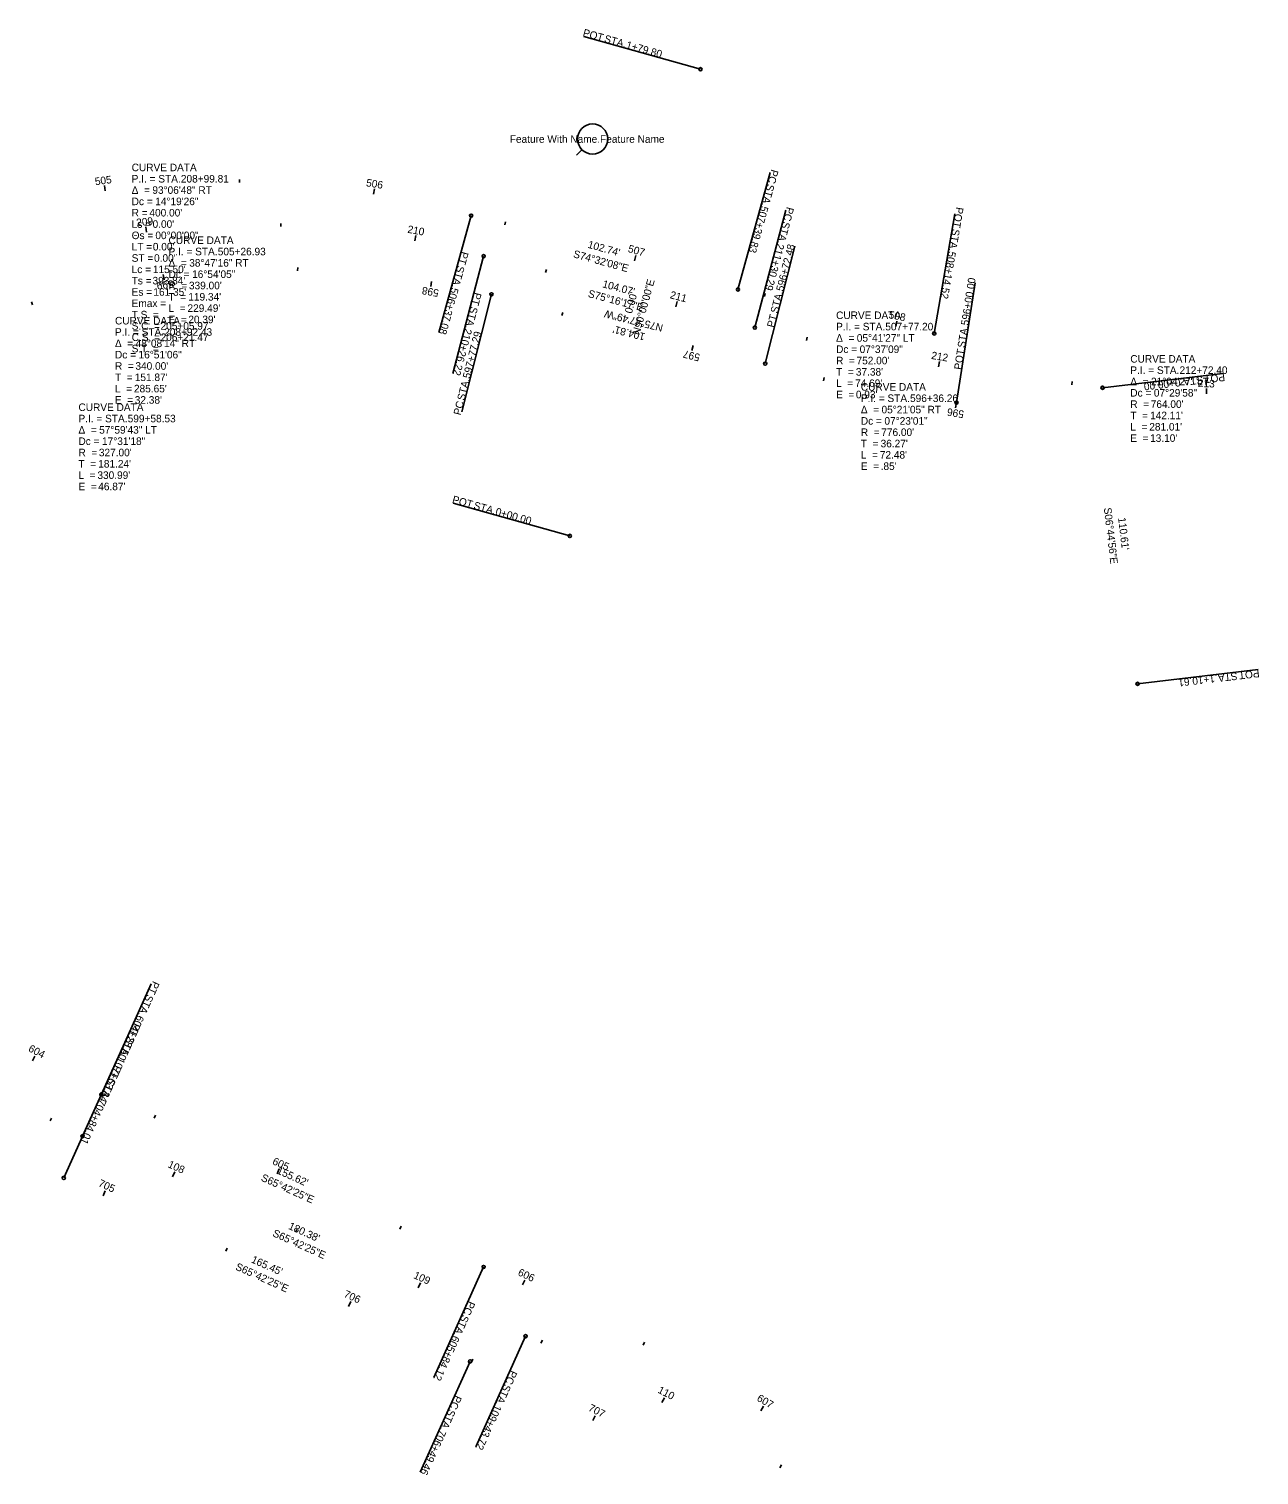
# Model space of a CAD drawing. Extents: x 1600023 to 1602131, y 285824 to 287284.
# Drawn here: x 1601230 to 1601686, y 286324 to 286860 of the extents above; entities that cross this region are included whole.
import ezdxf

# ---------------------------------------------------------------- set-up
doc = ezdxf.new("R2010")
doc.units = 0
for name, color, linetype in [('_CIVIL_CONSTRUCTION', 7, 'Continuous'), ('Default', 7, 'Continuous'), ('GE_P_Alignment', 7, 'Continuous'), ('PF_P_Grade_Line', 7, 'Continuous'), ('PF_X_Ground_Line', 7, 'Continuous'), ('PV_P_Curb', 7, 'Continuous'), ('SC_Scratch6', 7, 'Continuous'), ('SC_Scratch8', 7, 'Continuous')]:
    doc.layers.add(name, color=color, linetype=linetype)

msp = doc.modelspace()

# ---------------------------------------------------------------- linework, layer by layer
at = {"layer": '_CIVIL_CONSTRUCTION'}
for p, q in [((1601478.79, 286845.09), (1601435.46, 286857.22)), ((1601498.97, 286749.25), (1601510.41, 286792.77)), ((1601398.32, 286775.71), (1601386.88, 286732.19)), ((1601628.02, 286726.93), (1601672.71, 286732.22)), ((1601430.3, 286671.95), (1601386.97, 286684.09)), ((1601641.02, 286617.09), (1601685.71, 286622.38)), ((1601249.47, 286449.29), (1601267.99, 286490.31)), ((1601413.89, 286375.08), (1601395.37, 286334.07))]:
    msp.add_line(p, q, dxfattribs=at)
for centre in [(1601478.79, 286845.09), (1601398.32, 286775.71), (1601498.97, 286749.25), (1601628.02, 286726.93), (1601430.3, 286671.95), (1601641.02, 286617.09), (1601249.47, 286449.29), (1601413.89, 286375.08)]:
    msp.add_circle(centre, 0.6, dxfattribs=at)
at = {"layer": 'Default'}
for p, q in [((1601492.7, 286763.37), (1601504.69, 286806.74)), ((1601257.83, 286799.98), (1601257.57, 286801.96)), ((1601307.7, 286803.01), (1601307.71, 286804.21)), ((1601357.46, 286798.68), (1601357.78, 286800.65)), ((1601393.67, 286790.76), (1601381.67, 286747.39)), ((1601565.55, 286747.06), (1601573.19, 286791.41)), ((1601406.12, 286787.32), (1601406.44, 286788.48)), ((1601502.81, 286735.86), (1601513.85, 286779.49)), ((1601454.31, 286773.99), (1601454.84, 286775.92)), ((1601279.43, 286768.93), (1601279.69, 286766.94)), ((1601329.32, 286771.47), (1601329.29, 286770.27)), ((1601379.01, 286766.38), (1601378.66, 286764.42)), ((1601573.8, 286721.39), (1601580.73, 286765.85)), ((1601230.51, 286758.82), (1601230.85, 286757.66)), ((1601401.2, 286761.58), (1601390.16, 286717.96)), ((1601502.52, 286760.72), (1601502.82, 286761.88)), ((1601427.66, 286754.89), (1601427.36, 286753.72)), ((1601551.27, 286749.66), (1601551.65, 286751.63)), ((1601476.13, 286742.62), (1601475.64, 286740.68)), ((1601524.68, 286730.67), (1601524.42, 286729.49)), ((1601573.8, 286721.39), (1601573.49, 286719.41)), ((1601256.47, 286464.79), (1601274.98, 286505.8)), ((1601230.83, 286477.21), (1601231.75, 286478.99)), ((1601242.48, 286433.8), (1601260.99, 286474.81)), ((1601276.07, 286455.94), (1601276.56, 286457.03)), ((1601321.64, 286435.37), (1601322.46, 286437.19)), ((1601257.06, 286427.22), (1601257.88, 286429.04)), ((1601367.21, 286414.8), (1601367.71, 286415.89)), ((1601302.63, 286406.65), (1601303.12, 286407.74)), ((1601398.31, 286400.76), (1601379.8, 286359.75)), ((1601412.74, 286394.12), (1601413.59, 286395.93)), ((1601348.2, 286386.08), (1601349.03, 286387.9)), ((1601457.48, 286371.82), (1601458.04, 286372.88)), ((1601393.78, 286365.51), (1601394.27, 286366.6)), ((1601393.28, 286365.73), (1601374.77, 286324.71)), ((1601438.83, 286343.83), (1601439.74, 286345.61)), ((1601501.14, 286347.45), (1601502.15, 286349.17))]:
    msp.add_line(p, q, dxfattribs=at)
for centre in [(1601393.67, 286790.76), (1601492.7, 286763.37), (1601401.2, 286761.58), (1601565.55, 286747.06), (1601502.81, 286735.86), (1601573.8, 286721.39), (1601256.47, 286464.79), (1601242.48, 286433.8), (1601398.31, 286400.76), (1601393.28, 286365.73)]:
    msp.add_circle(centre, 0.6, dxfattribs=at)
at = {"layer": 'PV_P_Curb'}
msp.add_circle((1601438.76, 286819.18), 5.6, dxfattribs=at)
at = {"layer": 'SC_Scratch6'}
for p, q in [((1601273.15, 286784.67), (1601272.92, 286786.65)), ((1601323.06, 286786.69), (1601323.1, 286787.89)), ((1601372.73, 286781.39), (1601373.09, 286783.36)), ((1601421.32, 286769.66), (1601421.63, 286770.82)), ((1601469.68, 286756.95), (1601470.19, 286758.88)), ((1601518.1, 286744.48), (1601518.37, 286745.65)), ((1601567.11, 286734.62), (1601567.44, 286736.6)), ((1601616.66, 286727.99), (1601616.78, 286729.18)), ((1601666.53, 286724.61), (1601666.6, 286726.61)), ((1601237.38, 286454.93), (1601237.91, 286456.01)), ((1601282.89, 286434.21), (1601283.71, 286436.03)), ((1601328.46, 286413.64), (1601328.95, 286414.73)), ((1601374.03, 286393.07), (1601374.86, 286394.89)), ((1601419.6, 286372.48), (1601420.1, 286373.57)), ((1601464.5, 286350.5), (1601465.42, 286352.27)), ((1601508.25, 286326.3), (1601508.85, 286327.33))]:
    msp.add_line(p, q, dxfattribs=at)
at = {"layer": 'SC_Scratch8'}
msp.add_line((1601432.76, 286813.18), (1601434.8, 286815.22), dxfattribs=at)
msp.add_lwpolyline([(1601432.76, 286813.18), (1601433.47, 286813.89), (1601433.47, 286813.89)], close=True, dxfattribs=at)

# ---------------------------------------------------------------- texts
at = {"layer": '_CIVIL_CONSTRUCTION'}
for s, rotation, p in [('POT', 344.3549, (1601434.93, 286857.42)), (' STA. ', 344.3549, (1601441.86, 286855.47)), ('1+79.80', 344.3549, (1601450.96, 286852.92)), ('PC', 255.2715, (1601510.83, 286794.17)), (' STA. ', 255.2715, (1601509.66, 286789.74)), ('211+30.29', 255.2715, (1601507.26, 286780.6)), ('PT', 255.2715, (1601394.89, 286762.48)), (' STA. ', 255.2715, (1601393.77, 286758.21)), ('210+26.22', 255.2715, (1601391.36, 286749.07)), (' STA. ', 186.7488, (1601666.13, 286731.4)), ('POT', 186.7488, (1601673.28, 286732.24)), ('0+00.00', 186.7488, (1601656.74, 286730.29)), ('POT', 344.3549, (1601386.44, 286684.28)), (' STA. ', 344.3549, (1601393.37, 286682.34)), ('0+00.00', 344.3549, (1601402.47, 286679.79)), ('1+10.61', 186.7488, (1601669.54, 286620.42)), (' STA. ', 186.7488, (1601678.93, 286621.53)), ('POT', 186.7488, (1601686.08, 286622.38)), ('PT', 245.7068, (1601268.57, 286491.5)), (' STA. ', 245.7068, (1601266.76, 286487.48)), ('107+63.34', 245.7068, (1601262.87, 286478.86)), ('PC', 245.7068, (1601408.34, 286362.69)), (' STA. ', 245.7068, (1601406.45, 286358.51)), ('109+43.72', 245.7068, (1601402.56, 286349.9))]:
    msp.add_text(s, height=2.8, rotation=rotation, dxfattribs=at).set_placement(p)
at = {"layer": 'Default'}
for s, rotation, p in [('PC', 254.5355, (1601505.11, 286808.09)), ('505', 7.7047, (1601254.22, 286802.01)), ('506', 350.8033, (1601354.55, 286801.69)), (' STA. ', 254.5355, (1601503.89, 286803.67)), ('507+39.83', 254.5355, (1601501.37, 286794.57)), ('POT', 260.2263, (1601573.7, 286794.09)), (' STA. ', 260.2263, (1601572.48, 286786.99)), ("102.74'", 344.5355, (1601436.76, 286778.89)), ('507', 344.5355, (1601451.68, 286777.31)), ('596+72.48', 75.7969, (1601509.51, 286762.51)), ('PT', 254.5355, (1601390.09, 286777.64)), ('S74°32\'08"E', 344.5355, (1601431.36, 286775.36)), ('508+14.52', 260.2263, (1601570.87, 286777.68)), (' STA. ', 254.5355, (1601388.91, 286773.39)), ('599', 187.2981, (1601283.04, 286766.87)), ('598', 169.7764, (1601381.85, 286763.33)), ('506+37.08', 254.5355, (1601386.39, 286764.28)), ('596+00.00', 81.1483, (1601578.2, 286749.9)), (' STA. ', 75.7969, (1601507.19, 286753.34)), ('N75°47\'49"W', 165.7969, (1601465.12, 286750.35)), ('PT', 75.7969, (1601506.11, 286749.07)), ('508', 349.1202, (1601548.47, 286752.75)), ('597+77.29', 75.7969, (1601393.21, 286730.16)), ("104.81'", 165.7969, (1601458.47, 286747.04)), (' STA. ', 81.1483, (1601576.75, 286740.56)), ('597', 165.7969, (1601478.83, 286739.36)), ('POT', 81.1483, (1601575.64, 286733.45)), (' STA. ', 75.7969, (1601390.89, 286720.99)), ('PC', 75.7969, (1601389.76, 286716.55)), ('596', 171.1482, (1601576.73, 286718.4)), ('PT', 245.7068, (1601275.6, 286507.06)), (' STA. ', 245.7068, (1601273.78, 286503.04)), ('604+28.50', 245.7068, (1601269.89, 286494.43)), ('604', 332.5732, (1601229.08, 286480.94)), ('PT', 245.7068, (1601261.53, 286475.9)), (' STA. ', 245.7068, (1601259.71, 286471.87)), ('704+84.01', 245.7068, (1601255.83, 286463.26)), ('605', 335.7068, (1601319.66, 286439.01)), ("155.62'", 335.7068, (1601321.32, 286435.56)), ('705', 335.7068, (1601255.07, 286430.85)), ('S65°42\'25"E', 335.7068, (1601315.44, 286432.9)), ("165.45'", 335.7068, (1601311.81, 286402.55)), ('S65°42\'25"E', 335.7068, (1601305.94, 286399.89)), ('606', 334.8531, (1601410.76, 286397.81)), ('706', 335.7068, (1601346.17, 286389.74)), ('PC', 245.7068, (1601392.76, 286388.37)), (' STA. ', 245.7068, (1601390.88, 286384.19)), ('605+84.12', 245.7068, (1601386.99, 286375.58)), ('PC', 245.7068, (1601387.77, 286353.41)), ('607', 329.4783, (1601499.46, 286351.33)), (' STA. ', 245.7068, (1601385.88, 286349.23)), ('707', 332.9279, (1601436.92, 286347.61)), ('706+49.46', 245.7068, (1601382, 286340.61))]:
    msp.add_text(s, height=2.8, rotation=rotation, dxfattribs=at).set_placement(p)
for s, p in [('CURVE DATA', (1601281.37, 286780.25)), ('Δ  = ', (1601281.37, 286771.85)), ('P.I. = STA. ', (1601281.37, 286776.05)), ('38°47\'16" RT', (1601289.05, 286771.85)), ('505+26.93', (1601299.64, 286776.05)), ('Dc = ', (1601281.37, 286767.65)), ('16°54\'05"', (1601290.11, 286767.65)), ('R  = ', (1601281.37, 286763.45)), ("339.00'", (1601288.95, 286763.45)), ('T  = ', (1601281.37, 286759.25)), ("119.34'", (1601288.71, 286759.25)), ('L  = ', (1601281.37, 286755.05)), ('E  = ', (1601281.37, 286750.85)), ("229.49'", (1601288.41, 286755.05)), ("20.39'", (1601288.71, 286750.85)), ('CURVE DATA', (1601529.12, 286752.41)), ('P.I. = STA. ', (1601529.12, 286748.21)), ('507+77.20', (1601547.39, 286748.21)), ('Δ  = ', (1601529.12, 286744.01)), ('Dc = ', (1601529.12, 286739.81)), ('05°41\'27" LT', (1601536.8, 286744.01)), ('07°37\'09"', (1601537.86, 286739.81)), ('R  = ', (1601529.12, 286735.61)), ("752.00'", (1601536.71, 286735.61)), ('T  = ', (1601529.12, 286731.41)), ("37.38'", (1601536.46, 286731.41)), ('L  = ', (1601529.12, 286727.21)), ('E  = ', (1601529.12, 286723.01)), ("74.69'", (1601536.17, 286727.21)), ("0.93'", (1601536.46, 286723.01)), ('CURVE DATA', (1601538.31, 286725.83)), ('CURVE DATA', (1601247.94, 286718.3)), ('P.I. = STA. ', (1601538.31, 286721.63)), ('596+36.26', (1601556.57, 286721.63)), ('P.I. = STA. ', (1601247.94, 286714.1)), ('599+58.53', (1601266.21, 286714.1)), ('Δ  = ', (1601538.31, 286717.43)), ('Dc = ', (1601538.31, 286713.23)), ('05°21\'05" RT', (1601545.98, 286717.43)), ('07°23\'01"', (1601547.05, 286713.23)), ('Δ  = ', (1601247.94, 286709.9)), ('57°59\'43" LT', (1601255.62, 286709.9)), ('R  = ', (1601538.31, 286709.03)), ("776.00'", (1601545.89, 286709.03)), ('Dc = ', (1601247.94, 286705.7)), ("327.00'", (1601255.52, 286701.5)), ('17°31\'18"', (1601256.68, 286705.7)), ('T  = ', (1601538.31, 286704.83)), ("36.27'", (1601545.64, 286704.83)), ('T  = ', (1601247.94, 286697.3)), ('R  = ', (1601247.94, 286701.5)), ("181.24'", (1601255.28, 286697.3)), ('L  = ', (1601538.31, 286700.63)), ('E  = ', (1601538.31, 286696.43)), ("72.48'", (1601545.35, 286700.63)), (".85'", (1601545.65, 286696.43)), ('L  = ', (1601247.94, 286693.1)), ("330.99'", (1601254.98, 286693.1)), ('E  = ', (1601247.94, 286688.9)), ("46.87'", (1601255.28, 286688.9))]:
    msp.add_text(s, height=2.8, dxfattribs=at).set_placement(p)
at = {"layer": 'GE_P_Alignment'}
for s, rotation, p in [('N90°00\'00"E', 74.3549, (1601456.11, 286746.28)), ('S75°16\'17"E', 345.2715, (1601436.85, 286760.62)), ('S06°44\'56"E', 276.7488, (1601628.47, 286682.31)), ('S65°42\'25"E', 335.7068, (1601319.74, 286412.31))]:
    msp.add_text(s, height=2.8, rotation=rotation, dxfattribs=at).set_placement(p)
at = {"layer": 'PF_P_Grade_Line'}
for s, rotation, p in [("104.07'", 345.2715, (1601442.2, 286764.22)), ("0.00'", 74.3549, (1601453.31, 286754.25)), ("110.61'", 276.7488, (1601633.78, 286678.65)), ("180.38'", 335.7068, (1601325.61, 286414.97))]:
    msp.add_text(s, height=2.8, rotation=rotation, dxfattribs=at).set_placement(p)
at = {"layer": 'PF_X_Ground_Line'}
for s, p in [('CURVE DATA', (1601267.69, 286807.25)), ('Δ  = ', (1601267.69, 286798.85)), ('P.I. = STA. ', (1601267.69, 286803.05)), ('93°06\'48" RT', (1601275.37, 286798.85)), ('208+99.81', (1601285.96, 286803.05)), ('Dc = ', (1601267.69, 286794.65)), ('14°19\'26"', (1601276.43, 286794.65)), ('R = ', (1601267.69, 286790.45)), ("400.00'", (1601274.28, 286790.45)), ('Θs = ', (1601267.69, 286782.05)), ('Ls = ', (1601267.69, 286786.25)), ("0.00'", (1601275.45, 286786.25)), ('00°00\'00"', (1601276.49, 286782.05)), ('LT = ', (1601267.69, 286777.85)), ("0.00'", (1601275.55, 286777.85)), ('ST = ', (1601267.69, 286773.65)), ("0.00'", (1601276, 286773.65)), ('Lc = ', (1601267.69, 286769.45)), ("115.50'", (1601275.57, 286769.45)), ('Ts = ', (1601267.69, 286765.25)), ('Es = ', (1601267.69, 286761.05)), ("393.84'", (1601275.43, 286765.25)), ("161.35'", (1601275.75, 286761.05)), ('Emax = ', (1601267.69, 286756.85)), ('CURVE DATA', (1601261.5, 286750.4)), ('T.S. = ', (1601267.69, 286752.65)), ('P.I. = STA. ', (1601261.5, 286746.2)), ('S.C. = ', (1601267.69, 286748.45)), ('205+05.97', (1601278.41, 286748.45)), ('208+92.43', (1601279.76, 286746.2)), ('Δ  = ', (1601261.5, 286742)), ('S.T. = ', (1601267.69, 286740.05)), ('C.S. = ', (1601267.69, 286744.25)), ('48°08\'14" RT', (1601269.17, 286742)), ('206+21.47', (1601278.41, 286744.25)), ('Dc = ', (1601261.5, 286737.8)), ('16°51\'06"', (1601270.24, 286737.8)), ('CURVE DATA', (1601638.31, 286736.24)), ('T  = ', (1601261.5, 286729.4)), ('R  = ', (1601261.5, 286733.6)), ("151.87'", (1601268.84, 286729.4)), ("340.00'", (1601269.08, 286733.6)), ('P.I. = STA. ', (1601638.31, 286732.04)), ('212+72.40', (1601656.58, 286732.04)), ('L  = ', (1601261.5, 286725.2)), ("285.65'", (1601268.54, 286725.2)), ('Δ  = ', (1601638.31, 286727.84)), ('Dc = ', (1601638.31, 286723.64)), ('21°04\'27" LT', (1601645.99, 286727.84)), ('07°29\'58"', (1601647.05, 286723.64)), ('E  = ', (1601261.5, 286721)), ("32.38'", (1601268.84, 286721)), ('R  = ', (1601638.31, 286719.44)), ("764.00'", (1601645.89, 286719.44)), ('T  = ', (1601638.31, 286715.24)), ("142.11'", (1601645.65, 286715.24)), ('L  = ', (1601638.31, 286711.04)), ("281.01'", (1601645.35, 286711.04)), ('E  = ', (1601638.31, 286706.84)), ("13.10'", (1601645.65, 286706.84))]:
    msp.add_text(s, height=2.8, dxfattribs=at).set_placement(p)
at = {"layer": 'PV_P_Curb'}
msp.add_text('Feature With Name.Feature Name', height=2.8, dxfattribs=at).set_placement((1601408.02, 286817.78))
at = {"layer": 'SC_Scratch6'}
for s, rotation, p in [('209', 6.5413, (1601269.57, 286786.77)), ('210', 349.6896, (1601369.89, 286784.45)), ('211', 345.2715, (1601467.27, 286760.17)), ('212', 350.4996, (1601564.29, 286737.63)), ('213', 357.9991, (1601663.35, 286727.22)), ('108', 335.7068, (1601280.88, 286437.86)), ('109', 335.7068, (1601372.04, 286396.71)), ('110', 332.4824, (1601462.69, 286354.26))]:
    msp.add_text(s, height=2.8, rotation=rotation, dxfattribs=at).set_placement(p)

doc.saveas('drawing.dxf')
